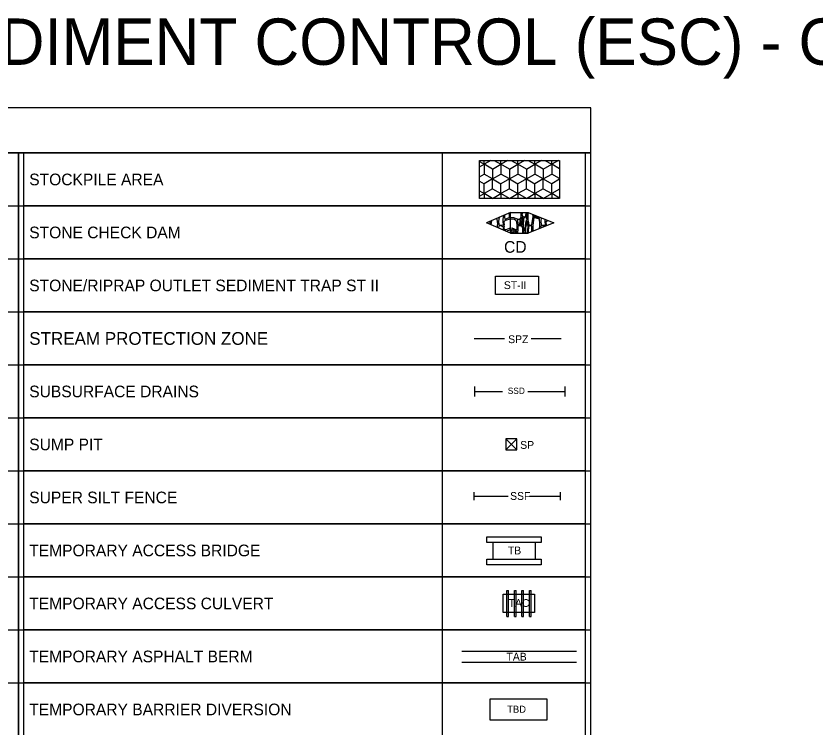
# Model space of a CAD drawing. Extents: x 1.3 to 34, y 0 to 22.5.
# Drawn here: x 12.78 to 20.33, y 14.4 to 21.12 of the extents above; entities that cross this region are included whole.
import ezdxf

# ---------------------------------------------------------------- set-up
doc = ezdxf.new("R2010")
doc.units = 0
for name, color, linetype in [('G-ANNO-NOTE', 7, 'Continuous'), ('G-ANNO-SYMB', 7, 'Continuous'), ('G-ANNO-TABL', 7, 'Continuous'), ('G-USER-LINE', 7, 'Continuous')]:
    doc.layers.add(name, color=color, linetype=linetype)

msp = doc.modelspace()

# ---------------------------------------------------------------- linework, layer by layer
at = {"layer": 'G-ANNO-SYMB'}
for p, q in [((17.15, 19.7434), (17.1938, 19.7181)), ((17.15, 19.6929), (17.1938, 19.7181)), ((17.1938, 19.7181), (17.1938, 19.7553)), ((17.2581, 19.7553), (17.1938, 19.7181)), ((17.1938, 19.7181), (17.1938, 19.626)), ((17.2736, 19.6721), (17.1938, 19.7181)), ((17.2736, 19.6721), (17.3534, 19.7181)), ((17.2891, 19.7553), (17.3534, 19.7181)), ((17.3534, 19.7181), (17.3534, 19.7553)), ((17.4177, 19.7553), (17.3534, 19.7181)), ((17.3534, 19.7181), (17.3534, 19.626)), ((17.4332, 19.6721), (17.3534, 19.7181)), ((17.4332, 19.6721), (17.513, 19.7181)), ((17.4488, 19.7553), (17.513, 19.7181)), ((17.513, 19.7181), (17.513, 19.7553)), ((17.5773, 19.7553), (17.513, 19.7181)), ((17.513, 19.7181), (17.513, 19.626)), ((17.5929, 19.6721), (17.513, 19.7181)), ((17.5929, 19.6721), (17.6727, 19.7181)), ((17.6084, 19.7553), (17.6727, 19.7181)), ((17.6727, 19.7181), (17.6727, 19.7553)), ((17.737, 19.7553), (17.6727, 19.7181)), ((17.6727, 19.7181), (17.6727, 19.626)), ((17.7525, 19.6721), (17.6727, 19.7181)), ((17.7525, 19.6721), (17.8323, 19.7181)), ((17.768, 19.7553), (17.8323, 19.7181)), ((17.8323, 19.7181), (17.8323, 19.7553)), ((17.8966, 19.7553), (17.8323, 19.7181)), ((17.8323, 19.7181), (17.8323, 19.626)), ((17.9068, 19.6751), (17.8323, 19.7181)), ((17.2736, 19.6721), (17.2736, 19.5799)), ((17.4332, 19.6721), (17.4332, 19.5799)), ((17.5929, 19.6721), (17.5929, 19.5799)), ((17.7525, 19.6721), (17.7525, 19.5799)), ((17.15, 19.6007), (17.1938, 19.626)), ((17.2736, 19.5799), (17.1938, 19.626)), ((17.2736, 19.5799), (17.1938, 19.5338)), ((17.2736, 19.5799), (17.3534, 19.626)), ((17.2736, 19.4877), (17.2736, 19.5799)), ((17.2736, 19.5799), (17.3534, 19.5338)), ((17.4332, 19.5799), (17.3534, 19.626)), ((17.4332, 19.5799), (17.3534, 19.5338)), ((17.4332, 19.5799), (17.513, 19.626)), ((17.4332, 19.4877), (17.4332, 19.5799)), ((17.4332, 19.5799), (17.513, 19.5338)), ((17.5929, 19.5799), (17.513, 19.626)), ((17.5929, 19.5799), (17.513, 19.5338)), ((17.5929, 19.5799), (17.6727, 19.626)), ((17.5929, 19.4877), (17.5929, 19.5799)), ((17.5929, 19.5799), (17.6727, 19.5338)), ((17.7525, 19.5799), (17.6727, 19.626)), ((17.7525, 19.5799), (17.6727, 19.5338)), ((17.7525, 19.5799), (17.8323, 19.626)), ((17.7525, 19.4877), (17.7525, 19.5799)), ((17.7525, 19.5799), (17.8323, 19.5338)), ((17.9068, 19.583), (17.8323, 19.626)), ((17.9068, 19.5768), (17.8323, 19.5338)), ((17.15, 19.5591), (17.1938, 19.5338)), ((17.1938, 19.4417), (17.1938, 19.5338)), ((17.2736, 19.4877), (17.1938, 19.4417)), ((17.2736, 19.4877), (17.3534, 19.4417)), ((17.3534, 19.4417), (17.3534, 19.5338)), ((17.4332, 19.4877), (17.3534, 19.4417)), ((17.4332, 19.4877), (17.513, 19.4417)), ((17.513, 19.4417), (17.513, 19.5338)), ((17.5929, 19.4877), (17.513, 19.4417)), ((17.5929, 19.4877), (17.6727, 19.4417)), ((17.6727, 19.4417), (17.6727, 19.5338)), ((17.7525, 19.4877), (17.6727, 19.4417)), ((17.7525, 19.4877), (17.8323, 19.4417)), ((17.8323, 19.4417), (17.8323, 19.5338)), ((17.9068, 19.4847), (17.8323, 19.4417)), ((17.15, 19.467), (17.1938, 19.4417)), ((17.15, 19.4164), (17.1938, 19.4417)), ((17.1938, 19.4417), (17.1938, 19.3947)), ((17.2736, 19.3956), (17.1938, 19.4417)), ((17.2736, 19.3956), (17.3534, 19.4417)), ((17.3534, 19.4417), (17.3534, 19.3947)), ((17.4332, 19.3956), (17.3534, 19.4417)), ((17.4332, 19.3956), (17.513, 19.4417)), ((17.513, 19.4417), (17.513, 19.3947)), ((17.5929, 19.3956), (17.513, 19.4417)), ((17.5929, 19.3956), (17.6727, 19.4417)), ((17.6727, 19.4417), (17.6727, 19.3947)), ((17.7525, 19.3956), (17.6727, 19.4417)), ((17.7525, 19.3956), (17.8323, 19.4417)), ((17.8323, 19.4417), (17.8323, 19.3947)), ((17.9068, 19.3987), (17.8323, 19.4417)), ((17.2736, 19.3956), (17.2736, 19.3947)), ((17.4332, 19.3956), (17.4332, 19.3947)), ((17.5929, 19.3956), (17.5929, 19.3947)), ((17.7525, 19.3956), (17.7525, 19.3947)), ((17.4433, 19.2624), (17.2163, 19.1644)), ((17.4433, 19.2624), (17.6107, 19.2624)), ((17.4433, 19.0674), (17.4433, 19.2624)), ((17.6107, 19.2624), (17.852, 19.1644)), ((17.6107, 19.0674), (17.6107, 19.2624)), ((17.4433, 19.0674), (17.2163, 19.1644)), ((17.852, 19.1644), (17.6107, 19.0674)), ((17.4433, 19.0674), (17.6107, 19.0674)), ((17.1, 18.075), (17.3855, 18.075)), ((17.6387, 18.075), (17.9229, 18.075)), ((17.1058, 17.575), (17.1058, 17.6222)), ((17.9589, 17.575), (17.9589, 17.6222)), ((17.1058, 17.5278), (17.1058, 17.575)), ((17.1058, 17.575), (17.369, 17.575)), ((17.6071, 17.575), (17.9589, 17.575)), ((17.9589, 17.5278), (17.9589, 17.575)), ((17.4, 17.0228), (17.5044, 17.1272)), ((17.4, 17.1272), (17.5044, 17.0228)), ((17.0988, 16.5874), (17.0988, 16.626)), ((17.9156, 16.5874), (17.9156, 16.626)), ((17.0988, 16.5488), (17.0988, 16.5874)), ((17.0994, 16.5874), (17.4217, 16.5874)), ((17.6229, 16.5874), (17.9162, 16.5874)), ((17.9156, 16.5488), (17.9156, 16.5874)), ((17.276, 16.1508), (17.276, 15.9914)), ((17.677, 16.1508), (17.677, 15.9915)), ((17.4086, 15.4521), (17.4086, 15.6979)), ((17.4086, 15.6979), (17.4233, 15.6979)), ((17.4233, 15.4521), (17.4233, 15.6979)), ((17.4806, 15.4521), (17.4806, 15.6979)), ((17.4806, 15.6979), (17.4953, 15.6979)), ((17.4953, 15.4521), (17.4953, 15.6979)), ((17.55, 15.4521), (17.55, 15.6979)), ((17.55, 15.6979), (17.5647, 15.6979)), ((17.5647, 15.4521), (17.5647, 15.6979)), ((17.6227, 15.4521), (17.6227, 15.6979)), ((17.6227, 15.6979), (17.6373, 15.6979)), ((17.6373, 15.4521), (17.6373, 15.6979)), ((17.4086, 15.4521), (17.4233, 15.4521)), ((17.4806, 15.4521), (17.4953, 15.4521)), ((17.55, 15.4521), (17.5647, 15.4521)), ((17.6227, 15.4521), (17.6373, 15.4521)), ((16.9844, 15.125), (18.0656, 15.125)), ((16.9844, 15.0225), (18.0656, 15.0225)), ((17.25, 14.4752), (17.25, 14.6748)), ((17.25, 14.6748), (17.7852, 14.6748)), ((17.7852, 14.6748), (17.7852, 14.4752)), ((17.7852, 14.4752), (17.25, 14.4752))]:
    msp.add_line(p, q, dxfattribs=at)
for points in [[(17.15, 19.7553), (17.9068, 19.7553), (17.9068, 19.3947), (17.15, 19.3947)], [(17.5314, 19.1424), (17.5347, 19.1941), (17.5259, 19.1974), (17.5105, 19.193), (17.5127, 19.1545), (17.5182, 19.1435)], [(17.5545, 19.1424), (17.56, 19.2062), (17.5512, 19.2217), (17.5413, 19.1908), (17.5391, 19.1457), (17.5435, 19.1424)], [(17.5017, 19.0718), (17.4697, 19.0862), (17.4532, 19.0873), (17.4554, 19.1027), (17.462, 19.1049), (17.5006, 19.0873)], [(17.3, 18.6613), (17.7083, 18.6613), (17.7083, 18.4887), (17.3, 18.4887)], [(17.4, 17.0228), (17.5044, 17.0228), (17.5044, 17.1272), (17.4, 17.1272)], [(17.2212, 16.2029), (17.7335, 16.2029), (17.7335, 16.15), (17.2212, 16.15)], [(17.2212, 15.9914), (17.7335, 15.9914), (17.7335, 15.9386), (17.2212, 15.9386)], [(17.375, 15.6612), (17.6688, 15.6612), (17.6688, 15.4888), (17.375, 15.4888)]]:
    msp.add_lwpolyline(points, close=True, dxfattribs=at)
for points in [[(17.5094, 19.2007), (17.4741, 19.2129), (17.4433, 19.214), (17.44, 19.2591), (17.4411, 19.2613)], [(17.5105, 19.2007), (17.5325, 19.204), (17.5413, 19.2129), (17.5446, 19.2261), (17.5424, 19.2437), (17.5446, 19.2624)], [(17.5556, 19.2624), (17.5512, 19.2393), (17.5589, 19.2261), (17.5667, 19.2206), (17.5865, 19.2283), (17.5898, 19.2624)], [(17.5997, 19.2624), (17.5931, 19.2294), (17.6019, 19.214), (17.6129, 19.1688), (17.6173, 19.1446)], [(17.2626, 19.1842), (17.2571, 19.1468)], [(17.321, 19.1401), (17.3221, 19.1567), (17.3177, 19.1996), (17.3067, 19.2029)], [(17.3364, 19.2162), (17.3309, 19.1809), (17.3342, 19.1479), (17.3761, 19.1435)], [(17.3761, 19.1435), (17.3728, 19.1853), (17.3761, 19.2327)], [(17.3849, 19.1401), (17.3827, 19.1776), (17.397, 19.1908), (17.4422, 19.204), (17.4807, 19.1996), (17.4939, 19.1919), (17.4984, 19.1765), (17.5017, 19.1401)], [(17.386, 19.2371), (17.3849, 19.2184), (17.3882, 19.1996)], [(17.3882, 19.1996), (17.4345, 19.2162), (17.4345, 19.2426), (17.4278, 19.2558)], [(17.5854, 19.1401), (17.5876, 19.1666), (17.5975, 19.2007), (17.592, 19.2184), (17.5733, 19.2173), (17.5667, 19.2018), (17.5633, 19.1401)], [(17.6173, 19.1446), (17.646, 19.1457), (17.657, 19.225), (17.6548, 19.2448)], [(17.7187, 19.1401), (17.7209, 19.1567), (17.7154, 19.1996), (17.6647, 19.2173), (17.6537, 19.1401)], [(17.6636, 19.2404), (17.6647, 19.2283), (17.7187, 19.2118)], [(17.7187, 19.2118), (17.7198, 19.2184)], [(17.733, 19.2129), (17.7286, 19.1809), (17.7319, 19.1479), (17.7749, 19.1435)], [(17.7749, 19.1435), (17.7704, 19.1853), (17.7715, 19.1974)], [(17.7826, 19.1401), (17.7804, 19.1776), (17.7925, 19.1886)], [(17.2494, 19.1501), (17.2538, 19.1809)], [(17.3199, 19.1203), (17.321, 19.139)], [(17.375, 19.0961), (17.3761, 19.1225), (17.375, 19.128), (17.3419, 19.1401), (17.332, 19.1346), (17.3309, 19.1159)], [(17.5017, 19.139), (17.5039, 19.1192), (17.5017, 19.0961), (17.4587, 19.1148), (17.4312, 19.1115), (17.3992, 19.0983), (17.3893, 19.0983), (17.3816, 19.1148), (17.3849, 19.139)], [(17.5578, 19.0674), (17.56, 19.0741), (17.5589, 19.1126), (17.5534, 19.1324), (17.5336, 19.1368), (17.5215, 19.1379), (17.5138, 19.1313), (17.5116, 19.1071), (17.5105, 19.0674)], [(17.5633, 19.139), (17.5655, 19.1115), (17.5667, 19.0774), (17.5744, 19.0707), (17.5843, 19.0685), (17.5821, 19.1082), (17.5854, 19.139)], [(17.5909, 19.0674), (17.5876, 19.0906), (17.5887, 19.1137), (17.5909, 19.139)], [(17.6063, 19.1401), (17.6041, 19.1666), (17.6019, 19.1776), (17.5975, 19.1798), (17.5931, 19.1655), (17.5909, 19.1401)], [(17.6063, 19.139), (17.603, 19.0939), (17.6041, 19.0674)], [(17.646, 19.0818), (17.646, 19.1005), (17.6449, 19.1346), (17.6316, 19.1379), (17.6184, 19.1368), (17.6129, 19.1236), (17.6096, 19.0873), (17.6107, 19.0674)], [(17.6537, 19.139), (17.6526, 19.1082), (17.6526, 19.084)], [(17.7176, 19.1104), (17.7187, 19.139)], [(17.7671, 19.1302), (17.7396, 19.1401), (17.7297, 19.1346), (17.7286, 19.1148)], [(17.7826, 19.1368), (17.7826, 19.139)], [(17.4003, 19.0862), (17.4014, 19.0884), (17.3948, 19.0884)], [(17.4102, 19.0818), (17.4179, 19.095), (17.4444, 19.1038), (17.4455, 19.0884), (17.4356, 19.0707)], [(17.4455, 19.0674), (17.4521, 19.0774), (17.4708, 19.0752), (17.484, 19.0674)]]:
    msp.add_lwpolyline(points, dxfattribs=at)
at = {"layer": 'G-ANNO-TABL'}
for p, q in [((2, 19.325), (18.2, 19.325)), ((2, 18.825), (18.2, 18.825)), ((2, 18.325), (18.2, 18.325)), ((2, 17.825), (18.2, 17.825)), ((2, 17.325), (18.2, 17.325)), ((2, 16.825), (18.2, 16.825)), ((2, 16.325), (18.2, 16.325)), ((2, 15.825), (18.2, 15.825)), ((2, 15.325), (18.2, 15.325)), ((2, 14.825), (18.2, 14.825))]:
    msp.add_line(p, q, dxfattribs=at)
for points in [[(2, 19.825), (18.2, 19.825), (18.2, 20.25), (2, 20.25)], [(7.4, 7.825), (12.8, 7.825), (12.8, 19.825), (7.4, 19.825)], [(12.8, 7.825), (18.2, 7.825), (18.2, 19.825), (12.8, 19.825)]]:
    msp.add_lwpolyline(points, close=True, dxfattribs=at)
at = {"layer": 'G-USER-LINE'}
for p, q in [((12.85, 19.325), (12.85, 19.825)), ((16.8, 19.825), (12.85, 19.825)), ((16.8, 19.325), (16.8, 19.825)), ((18.15, 19.825), (16.8, 19.825)), ((18.15, 19.325), (18.15, 19.825)), ((12.85, 18.825), (12.85, 19.325)), ((16.8, 19.325), (12.85, 19.325)), ((16.8, 18.825), (16.8, 19.325)), ((18.15, 19.325), (16.8, 19.325)), ((18.15, 18.825), (18.15, 19.325)), ((12.85, 18.325), (12.85, 18.825)), ((16.8, 18.825), (12.85, 18.825)), ((18.15, 18.825), (16.8, 18.825)), ((16.8, 18.325), (16.8, 18.825)), ((18.15, 18.325), (18.15, 18.825)), ((12.85, 17.825), (12.85, 18.325)), ((16.8, 18.325), (12.85, 18.325)), ((18.15, 18.325), (16.8, 18.325)), ((16.8, 17.825), (16.8, 18.325)), ((18.15, 17.825), (18.15, 18.325)), ((12.85, 17.325), (12.85, 17.825)), ((16.8, 17.825), (12.85, 17.825)), ((18.15, 17.825), (16.8, 17.825)), ((16.8, 17.325), (16.8, 17.825)), ((18.15, 17.325), (18.15, 17.825)), ((12.85, 16.825), (12.85, 17.325)), ((16.8, 17.325), (12.85, 17.325)), ((18.15, 17.325), (16.8, 17.325)), ((16.8, 16.825), (16.8, 17.325)), ((18.15, 16.825), (18.15, 17.325)), ((12.85, 16.325), (12.85, 16.825)), ((16.8, 16.825), (12.85, 16.825)), ((18.15, 16.825), (16.8, 16.825)), ((16.8, 16.325), (16.8, 16.825)), ((18.15, 16.325), (18.15, 16.825)), ((12.85, 15.825), (12.85, 16.325)), ((16.8, 16.325), (12.85, 16.325)), ((18.15, 16.325), (16.8, 16.325)), ((16.8, 15.825), (16.8, 16.325)), ((18.15, 15.825), (18.15, 16.325)), ((12.85, 15.325), (12.85, 15.825)), ((16.8, 15.825), (12.85, 15.825)), ((18.15, 15.825), (16.8, 15.825)), ((16.8, 15.325), (16.8, 15.825)), ((18.15, 15.325), (18.15, 15.825)), ((12.85, 14.825), (12.85, 15.325)), ((16.8, 15.325), (12.85, 15.325)), ((18.15, 15.325), (16.8, 15.325)), ((16.8, 14.825), (16.8, 15.325)), ((18.15, 14.825), (18.15, 15.325)), ((16.8, 14.825), (12.85, 14.825)), ((12.85, 14.325), (12.85, 14.825)), ((18.15, 14.825), (16.8, 14.825)), ((16.8, 14.325), (16.8, 14.825)), ((18.15, 14.325), (18.15, 14.825))]:
    msp.add_line(p, q, dxfattribs=at)

# ---------------------------------------------------------------- texts
at = {"layer": 'G-ANNO-NOTE'}
msp.add_text('EROSION AND SEDIMENT CONTROL (ESC) - GENERAL NOTES', height=0.4375, dxfattribs=at).set_placement((7.5826, 20.6562))
at = {"layer": 'G-ANNO-SYMB'}
for s, height, p in [(' CD', 0.11016, (17.3413, 18.8835)), ('ST-II', 0.07344, (17.3805, 18.5409)), ('SPZ', 0.07344, (17.4212, 18.0308)), ('SSD', 0.05875, (17.4173, 17.552)), ('SP', 0.07344, (17.5351, 17.0338)), ('SSF', 0.07344, (17.4394, 16.552)), ('TB', 0.07344, (17.4184, 16.0383)), ('TAC', 0.07344, (17.4254, 15.5423)), ('TAB', 0.07344, (17.4053, 15.0362)), ('TBD', 0.0661, (17.4124, 14.5441))]:
    msp.add_text(s, height=height, dxfattribs=at).set_placement(p)
at = {"layer": 'G-ANNO-TABL'}
for s, height, p in [('STOCKPILE AREA', 0.11, (12.9, 19.52)), ('STONE CHECK DAM', 0.11, (12.9, 19.02)), ('STONE/RIPRAP OUTLET SEDIMENT TRAP ST II', 0.11, (12.9, 18.52)), ('STREAM PROTECTION ZONE', 0.12, (12.9, 18.015)), ('SUBSURFACE DRAINS', 0.11, (12.9, 17.52)), ('SUMP PIT', 0.11, (12.9, 17.02)), ('SUPER SILT FENCE', 0.11, (12.9, 16.52)), ('TEMPORARY ACCESS BRIDGE', 0.11, (12.9, 16.02)), ('TEMPORARY ACCESS CULVERT', 0.11, (12.9, 15.52)), ('TEMPORARY ASPHALT BERM', 0.11, (12.9, 15.02)), ('TEMPORARY BARRIER DIVERSION', 0.11, (12.9, 14.52))]:
    msp.add_text(s, height=height, dxfattribs=at).set_placement(p)

doc.saveas('drawing.dxf')
